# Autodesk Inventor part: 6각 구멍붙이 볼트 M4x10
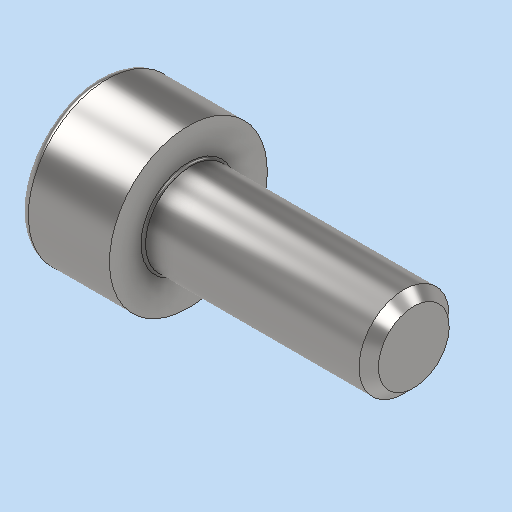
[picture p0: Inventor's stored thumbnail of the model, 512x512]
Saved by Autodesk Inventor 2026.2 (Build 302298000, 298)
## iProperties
Created: 2026-01
Part Number: 6각 구멍붙이 볼트 M4x10
Material: 강철, 연강
Description: 6각머리 태핑 나사
Document SubType Name: Modeling
Designer: PC2-07
Density: 7.85 g/cm^3
Appearance: 기본값
Sending System: Autodesk Inventor 2026
Preprocessor: ST-DEVELOPER v20.1
Author: jhkim
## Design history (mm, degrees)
feature "Solid1"
node "솔리드1"
